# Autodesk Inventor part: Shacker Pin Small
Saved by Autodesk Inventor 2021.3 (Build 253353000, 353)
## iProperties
Created: 2022-03
Part Number: Shacker Pin Small
Material: Generic
Document SubType Name: Modeling
Designer: Administrator
Density: 1 g/cm^3
Appearance: Default
Title: Shacker Pin Small v1
Author: Administrator
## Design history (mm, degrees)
feature "Body1"
body "Solid1"
